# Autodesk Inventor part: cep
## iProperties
Shininess: 64.0
Length Units: 11269
Angle Units: 11279
Time Units: 11290
Mass Units: 11283
Length Display Precision: 3
Angle Display Precision: 2
Compacted: True
Part Number: cep
Document SubType Name: Modeling
Created: 2003-06
Material: Výchozí
Density: 0.0
Volumn: 0.0
Area: 0.0
PropertySet Name: Model Information
Control State: 0
Master: False
Checked Out: False
Title: čep
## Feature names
1. Vysunutí1 [Extrusion]
